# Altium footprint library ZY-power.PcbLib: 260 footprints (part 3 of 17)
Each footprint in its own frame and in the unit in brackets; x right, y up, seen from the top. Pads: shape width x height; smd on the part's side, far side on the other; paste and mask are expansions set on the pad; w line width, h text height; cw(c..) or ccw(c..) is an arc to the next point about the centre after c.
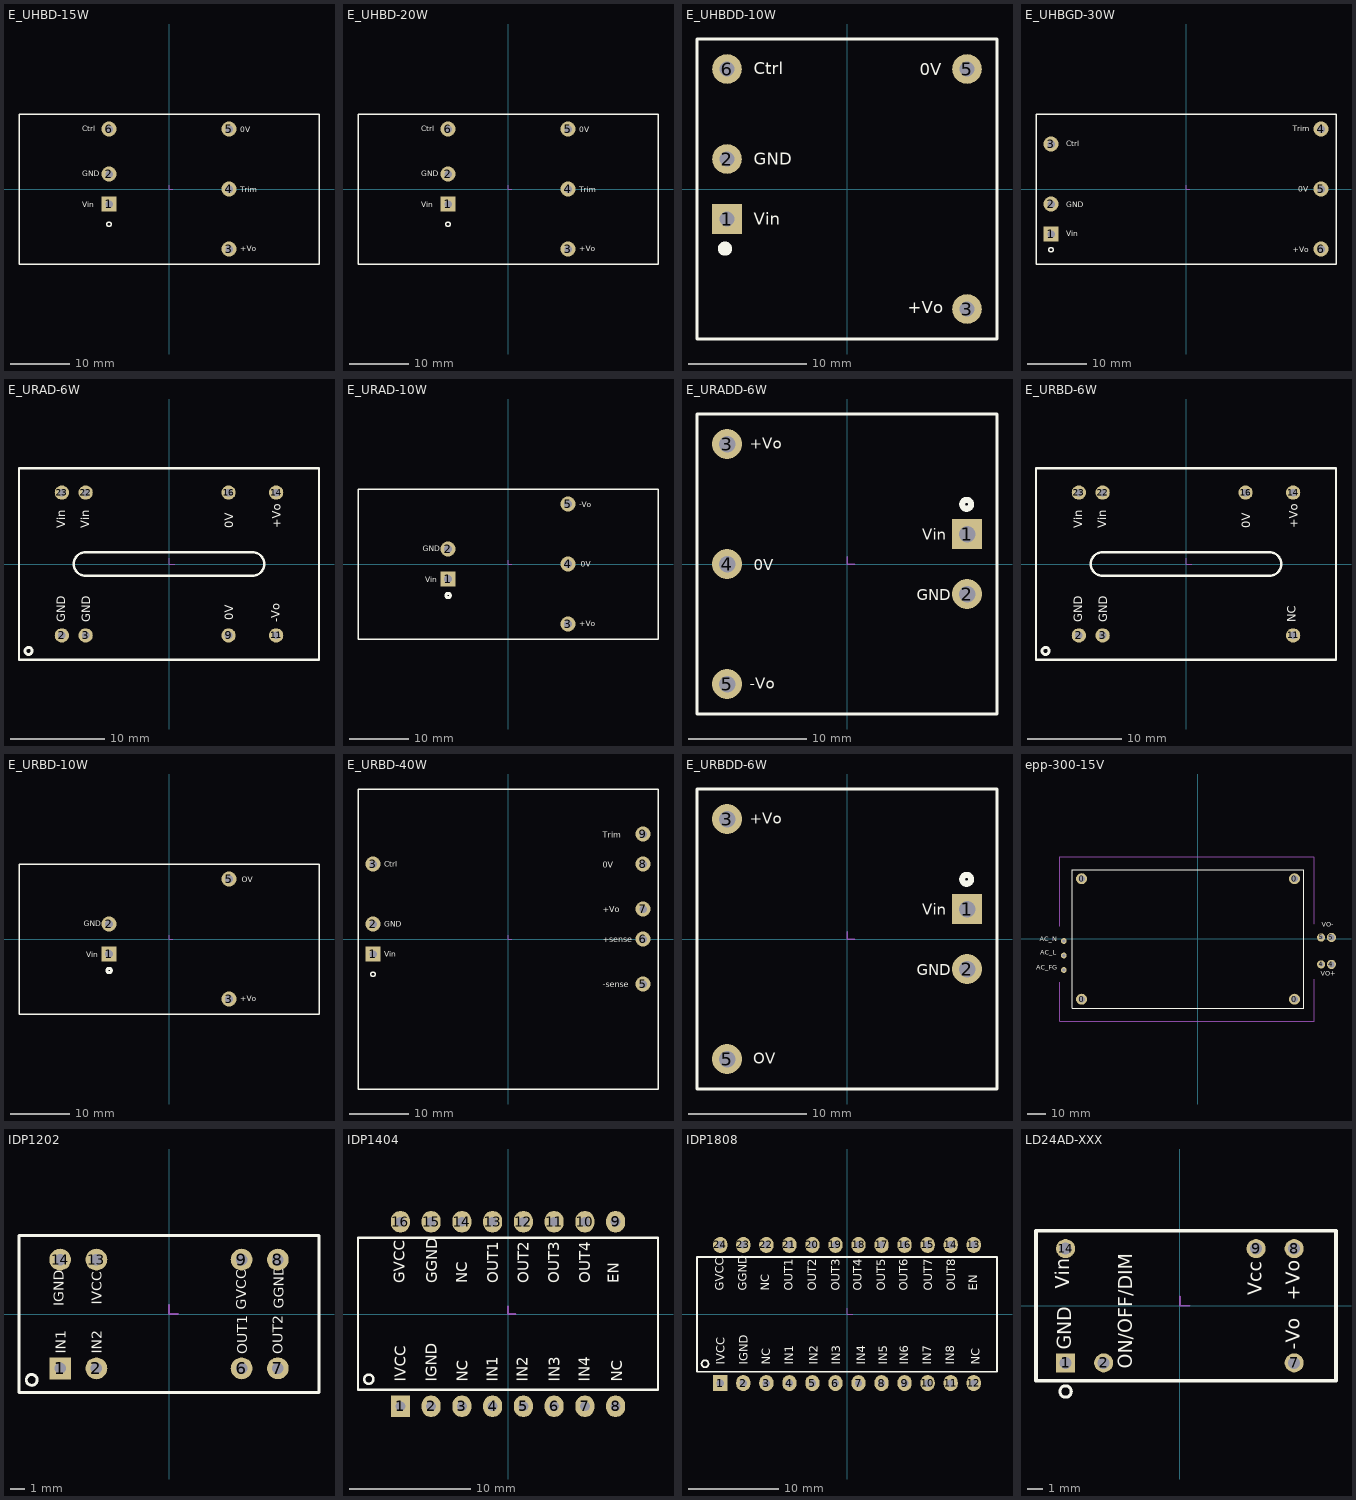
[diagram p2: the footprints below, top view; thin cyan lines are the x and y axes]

## E_UHBD-15W [mil]
pads (6):
  rect 100x100 hole 50: 1(-400,-100)
  round 100 hole 50: 2(-400,100) 3(400,-400) 4(400,0) 5(400,400) 6(-400,400)
Top Overlay:
  circle w10: c-400,-235 r15
  lines w10: -1000,-500 1000,-500 1000,500 -1000,500 -1000,-500
  text "Ctrl" at -580,385 h36
  text "Trim" at 475,-20 h36
  text "Vin" at -580,-120 h36
  text "GND" at -580,85 h36
  text "0V" at 475,380 h36
  text "+Vo" at 475,-415 h36
Mechanical 15:
  lines w5: 0,25 0,0 25,0

## E_UHBD-20W [mil]
pads (6):
  rect 100x100 hole 50: 1(-400,-100)
  round 100 hole 50: 2(-400,100) 3(400,-400) 4(400,0) 5(400,400) 6(-400,400)
Top Overlay:
  circle w10: c-400,-235 r15
  lines w10: -1000,-500 -1000,500 1000,500 1000,-500 -1000,-500
  text "+Vo" at 475,-415 h36
  text "0V" at 475,380 h36
  text "GND" at -580,85 h36
  text "Vin" at -580,-120 h36
  text "Trim" at 475,-20 h36
  text "Ctrl" at -580,385 h36
Mechanical 15:
  lines w5: 0,25 0,0 25,0

## E_UHBDD-10W [mm]
height 11.7
pads (5):
  rect 2.5x2.5 hole 1.3: 1(-10.16,-2.54)
  round 2.5 hole 1.3: 2(-10.16,2.54) 3(10.16,-10.16) 5(10.16,10.16) 6(-10.16,10.16)
Top Overlay:
  circle w1: c-10.331,-5.05 r0.1
  lines w0.254: -12.7,-12.7 -12.7,12.7 12.7,12.7 12.7,-12.7 -12.7,-12.7
  text "GND" at -7.9,2.05 h1.02
  text "Vin" at -7.9,-3.025 h1.02
  text "Ctrl" at -7.9,9.7 h1.02
  text "+Vo" at 5.15,-10.5 h1.02
  text "0V" at 6.175,9.625 h1.02

## E_UHBGD-30W [mil]
height 500
pads (6):
  rect 100x100 hole 50: 1(-900,-300)
  round 100 hole 50: 2(-900,-100) 3(-900,300) 4(900,400) 5(900,0) 6(900,-400)
Top Overlay:
  circle w10: c-900,-405 r15
  lines w10: -1000,-500 1000,-500 1000,500 -1000,500 -1000,-500
  text "Ctrl" at -800,285 h36
  text "Trim" at 710,385 h36
  text "Vin" at -800,-315 h36
  text "GND" at -800,-120 h36
  text "0V" at 746.68,-17.5 h36
  text "+Vo" at 710.34,-420 h36
Mechanical 15:
  lines w5: 0,25 0,0 25,0

## E_URAD-6W [mil]
height 433.07
pads (8):
  round 60 hole 32: 2(-450,-300) 3(-350,-300) 9(250,-300) 11(450,-300) 14(450,300) 16(250,300) 22(-350,300) 23(-450,300)
Top Overlay:
  circle w12: c-590,-365 r15
  lines w10: -629.92,-401.57 -629.92,401.57 629.92,401.57 629.92,-401.57 -629.92,-401.57 ; -400,0 ccw(c-350,0) -350,-50 350,-50 ccw(c350,0) 400,0 ccw(c350,0) 350,50 -350,50 ccw(c-350,0) -400,0
  text "GND" at -435,-245 h36
  text "GND" at -330,-245 h36
  text "Vin" at -435,150 h36
  text "Vin" at -335,150 h36
  text "-Vo" at 465,-245 h36
  text "+Vo" at 470,150 h36
  text "0V" at 270,150 h36
  text "0V" at 269,-237 h36
Mechanical 15:
  lines w5: 0,25 0,0 25,0

## E_URAD-10W [mil]
height 500
pads (5):
  rect 100x100 hole 55: 1(-400,-100)
  round 100 hole 55: 2(-400,100) 3(400,-400) 4(400,0) 5(400,400)
Top Overlay:
  circle w20: c-399,-210 r15
  lines w10: -1000,-500 -1000,500 1000,500 1000,-500 -1000,-500
  text "+Vo" at 475,-415 h36
  text "-Vo" at 475,380 h36
  text "GND" at -568,85 h36
  text "Vin" at -551,-120 h36
  text "0V" at 486,-19 h36
Mechanical 15:
  lines w5: 0,25 0,0 25,0

## E_URADD-6W [mil]
height 460.63
pads (5):
  rect 100x100 hole 55: 1(400,100)
  round 100 hole 55: 2(400,-100) 3(-400,400) 4(-400,0) 5(-400,-400)
Top Overlay:
  circle w20: c399,199 r15
  lines w10: -500,-500 -500,500 500,500 500,-500 -500,-500
  text "+Vo" at -324,384 h36
  text "-Vo" at -324,-416 h36
  text "0V" at -311,-21 h36
  text "GND" at 232,-121 h36
  text "Vin" at 250,81 h36
Mechanical 15:
  lines w5: 0,25 0,0 25,0

## E_URBD-6W [mil]
height 433.07
pads (7):
  round 60 hole 32: 2(-450,-300) 3(-350,-300) 11(450,-300) 14(450,300) 16(250,300) 22(-350,300) 23(-450,300)
Top Overlay:
  circle w12: c-590,-365 r15
  lines w10: -629.92,-401.57 629.92,-401.57 629.92,401.57 -629.92,401.57 -629.92,-401.57 ; -400,0 cw(c-350,0) -350,50 350,50 cw(c350,0) 400,0 cw(c350,0) 350,-50 -350,-50 cw(c-350,0) -400,0
  text "0V" at 270,150 h36
  text "+Vo" at 470,150 h36
  text "NC" at 460,-245 h36
  text "Vin" at -335,150 h36
  text "Vin" at -435,150 h36
  text "GND" at -330,-245 h36
  text "GND" at -435,-245 h36
Mechanical 15:
  lines w5: 0,25 0,0 25,0

## E_URBD-10W [mil]
height 500
pads (4):
  rect 100x100 hole 55: 1(-400,-100)
  round 100 hole 55: 2(-400,100) 3(400,-400) 5(400,400)
Top Overlay:
  circle w20: c-399,-210 r15
  lines w10: -1000,-500 1000,-500 1000,500 -1000,500 -1000,-500
  text "Vin" at -551,-120 h36
  text "GND" at -568,85 h36
  text "OV" at 485,380 h36
  text "+Vo" at 475,-415 h36
Mechanical 15:
  lines w5: 0,25 0,0 25,0

## E_URBD-40W [mil]
height 440.94
pads (8):
  rect 100x100 hole 50: 1(-900,-100)
  round 100 hole 50: 2(-900,100) 3(-900,500) 5(900,-300) 6(900,0) 7(900,200) 8(900,500) 9(900,700)
Top Overlay:
  circle w10: c-900,-235 r15
  lines w10: -1000,-1000 1000,-1000 1000,1000 -1000,1000 -1000,-1000
  text "Trim" at 630,675 h40
  text "Ctrl" at -825,480.08 h36
  text "-sense" at 630,-320 h40
  text "+sense" at 630,-20 h40
  text "Vin" at -825,-119.92 h36
  text "GND" at -825,80.08 h36
  text "0V" at 630,475 h40
  text "+Vo" at 630,180 h40
Mechanical 15:
  lines w5: 0,25 0,0 25,0

## E_URBDD-6W [mil]
height 460.63
pads (4):
  rect 100x100 hole 55: 1(400,100)
  round 100 hole 55: 2(400,-100) 3(-400,400) 5(-400,-400)
Top Overlay:
  circle w20: c399,199 r15
  lines w10: -500,-500 500,-500 500,500 -500,500 -500,-500
  text "Vin" at 250,81 h36
  text "GND" at 232,-121 h36
  text "OV" at -313,-416 h36
  text "+Vo" at -324,384 h36
Mechanical 15:
  lines w5: 0,25 0,0 25,0

## epp-300-15V [mm]
height 22
pads (11):
  round 6 hole 3.6: 0(-63.785,-33.1) 0(-63.785,33.1) 0(53.215,-33.1) 0(53.215,33.1)
  round 3.2 hole 1.8: 1(-73.516,-1.134) 2(-73.516,-9.08) 3(-73.516,-17.076)
  round 4.5 hole 2.5: 4(67.846,-13.956) 5(67.846,0.813)
  round 5 hole 3.2: 4(73.516,-13.95) 5(73.516,0.825)
Top Overlay:
  lines w0.203: -68.785,-38.1 -68.785,38.1 58.215,38.1 58.215,-37.846 58.215,-38.1 -68.785,-38.1
  text "AC_L" at -86.487,-9.779 h4.5
  text "AC_N" at -86.843,-2.311 h4.5
  text "AC_FG" at -88.798,-18.11 h4.5
  text "VO-" at 68.301,5.563 h4.5
  text "VO+" at 67.539,-21.438 h4.5
Mechanical 15:
  lines w0.203: -75.785,-45.1 -75.785,-23.9 ; -75.785,6.875 -75.785,12.15 ; -75.785,11.7 -75.785,25.875 ; -75.785,25.675 -75.785,45.025 ; -75.785,45.05 -47.735,45.05 -33.56,45.05 64.191,45.05 ; -75.735,-45.1 -56.06,-45.1 -41.885,-45.1 64.191,-45.1 64.191,-22.175 ; 64.191,8.2 64.191,24.575 ; 64.191,24.275 64.191,45.026

## IDP1202 [mil] "20x10x8mm"
height 315
pads (8):
  rect 60x60 hole 32: 1(-300,-150)
  round 60 hole 32: 2(-200,-150) 6(200,-150) 7(300,-149.7) 8(300,150) 9(200,150) 13(-200,150) 14(-300,150)
Top Overlay:
  circle w8: c-378.39,-181.54 r15
  lines w8: -413.39,-216.54 -413.39,216.54 413.39,216.54 413.39,-216.54 -413.39,-216.54
  text "IN2" at -185,-110 h28
  text "IN1" at -285,-110 h28
  text "OUT1" at 215,-111 h28
  text "OUT2" at 314,-111 h28
  text "GGND" at 316,14 h28
  text "GVCC" at 213,12 h28
  text "IVCC" at -186,26 h28
  text "IGND" at -290,22 h28
Mechanical 15:
  lines w5: 0,25 0,0 25,0

## IDP1404 [mil] "23.97x14.41x9.65mm"
height 380
pads (16):
  rect 62x70 hole 32: 1(-350,-300)
  oval 62x70 hole 32: 2(-250,-300) 3(-150,-300) 4(-50,-300) 5(50,-300) 6(150,-300) 7(250,-300) 8(350,-300) 9(350,300) 10(250,300) 11(150,300) 12(50,300) 13(-50,300) 14(-150,300) 15(-250,300) 16(-350,300)
Top Overlay:
  circle w8: c-452.8,-212 r15
  lines w8: -487.8,-247 487.8,-247 487.8,248 -487.8,248 -487.8,-247
  text "IVCC" at -333,-220 h36
  text "IGND" at -231,-220 h36
  text "NC" at -131,-220 h36
  text "IN1" at -34,-220 h36
  text "IN2" at 65,-220 h36
  text "IN3" at 168,-220 h36
  text "IN4" at 266,-220 h36
  text "NC" at 372,-220 h36
  text "EN" at 360,100 h36
  text "OUT1" at -32,100 h36
  text "OUT2" at 67,100 h36
  text "OUT3" at 166,100 h36
  text "OUT4" at 267,100 h36
  text "NC" at -133,100 h36
  text "GGND" at -230,100 h36
  text "GVCC" at -335,100 h36
Mechanical 15:
  lines w5: 0,25 0,0 25,0

## IDP1808 [mil] "32.32x14.41x6.7(9.65)mm"
height 246
pads (24):
  rect 62x70 hole 32: 1(-550,-300)
  oval 62x70 hole 32: 2(-450,-300) 3(-350,-300) 4(-250,-300) 5(-150,-300) 6(-50,-300) 7(50,-300) 8(150,-300) 9(250,-300) 10(350,-300) 11(450,-300) 12(550,-300) 13(550,300) 14(450,300) 15(350,300) 16(250,300) 17(150,300) 18(50,300) 19(-50,300) 20(-150,300) 21(-250,300) 22(-350,300) 23(-450,300) 24(-550,300)
Top Overlay:
  circle w8: c-616.18,-216 r15
  lines w8: -651.18,-251 -651.18,248 651.18,248 651.18,-251 -651.18,-251
  text "NC" at -337,100 h36
  text "GGND" at -435,100 h36
  text "GVCC" at -535,100 h36
  text "OUT8" at 469,100 h36
  text "OUT7" at 371,100 h36
  text "OUT6" at 264,100 h36
  text "OUT5" at 167,100 h36
  text "OUT4" at 65,100 h36
  text "OUT3" at -32,100 h36
  text "OUT2" at -134,100 h36
  text "OUT1" at -235,100 h36
  text "EN" at 566,100 h36
  text "NC" at 577,-220 h36
  text "IN8" at 465,-220 h36
  text "IN7" at 366,-220 h36
  text "IN6" at 266,-220 h36
  text "IN5" at 174,-220 h36
  text "IN4" at 79,-220 h36
  text "IN3" at -29,-220 h36
  text "IN2" at -128,-220 h36
  text "IN1" at -233,-220 h36
  text "NC" at -334,-220 h36
  text "IGND" at -431,-220 h36
  text "IVCC" at -531,-220 h36
Mechanical 15:
  lines w5: 0,25 0,0 25,0

## LD24AD-XXX [mil]
pads (6):
  rect 50x50 hole 32: 1(-300,-150)
  round 50 hole 32: 2(-200,-150) 7(300,-150) 8(300,150) 9(200,150) 14(-300,150)
Top Overlay:
  circle w8: c-300,-225 r15
  lines w10: -377.56,-196.85 409.84,-196.85 409.84,196.85 -377.56,196.85 -377.56,-196.85
  text "ON/OFF/DIM" at -125,-165 h36
  text "Vin" at -290,45 h36
  text "GND" at -285,-115 h36
  text "Vcc" at 215,28.2 h36
  text "+Vo" at 315,13.29 h36
  text "-Vo" at 315,-115 h36
Mechanical 15:
  lines w5: 0,25 0,0 25,0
